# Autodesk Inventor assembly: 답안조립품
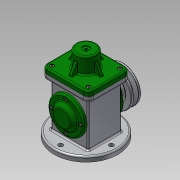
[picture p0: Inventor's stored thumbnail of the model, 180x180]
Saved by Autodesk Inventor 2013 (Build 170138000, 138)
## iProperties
Created: 2018-10
Part Number: 답안조립품
Document SubType Name: Assembly
Designer: hana-max6
Author: hana-max6
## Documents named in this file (18)
- C:\Documents and Settings\hana-max6\바탕 화면\481007V1057\답안조립품.iam
- C:\Documents and Settings\hana-max6\바탕 화면\481007V1057\V-벨트풀리.ipt
- C:\Documents and Settings\hana-max6\바탕 화면\481007V1057\덮개.ipt
- C:\Documents and Settings\hana-max6\바탕 화면\481007V1057\뒤커버.ipt
- C:\Documents and Settings\hana-max6\바탕 화면\481007V1057\링크.ipt
- C:\Documents and Settings\hana-max6\바탕 화면\481007V1057\베어링 17 x 40 x 12.ipt
- C:\Documents and Settings\hana-max6\바탕 화면\481007V1057\본체.ipt
- C:\Documents and Settings\hana-max6\바탕 화면\481007V1057\볼트 M4 x 8.ipt
- C:\Documents and Settings\hana-max6\바탕 화면\481007V1057\볼트 M4 x 10.ipt
- C:\Documents and Settings\hana-max6\바탕 화면\481007V1057\슬라이더.ipt
- C:\Documents and Settings\hana-max6\바탕 화면\481007V1057\앞커버.ipt
- C:\Documents and Settings\hana-max6\바탕 화면\481007V1057\오일 실 17 30 8.ipt
- C:\Documents and Settings\hana-max6\바탕 화면\481007V1057\와셔 4x16.ipt
- C:\Documents and Settings\hana-max6\바탕 화면\481007V1057\클레비스 핀 6 x 22.ipt
- 클레비스 핀 6 x 22.ipt
- C:\Documents and Settings\hana-max6\바탕 화면\481007V1057\키 4 x 4 x 12.ipt
- C:\Documents and Settings\hana-max6\바탕 화면\481007V1057\편심축.ipt
- C:\Documents and Settings\hana-max6\바탕 화면\481007V1057\E-링.ipt
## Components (2 placed, 2 different names)
1. V-벨트풀리:1 — 각도:2
2. E-링:1
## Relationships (1: Angle 1)
- 각도:2 [Angle]: V-벨트풀리:1
